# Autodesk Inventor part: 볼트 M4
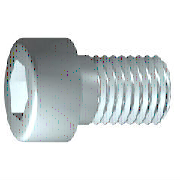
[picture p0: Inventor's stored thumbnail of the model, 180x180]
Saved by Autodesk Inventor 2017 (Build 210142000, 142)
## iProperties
IsCustomPart: 0
Created: 2012-02
Part Number: 볼트 M4
Material: 강철, 연강
Description: 6각 소켓 머리 캡 나사
Document SubType Name: Modeling
Standard: ISO 4762
Designer: mduedu
Standard Revision: Fourth edition 2004-03-01
Standards Organization: ISO
Language: ko-KR
Size Designation: M4 x 12
Categories: <MemberInstance><Categories><Category DisplayName="조임쇠" InternalName="e4da775c-781d-43d5-af7c-5136215cf5a6" Mnemonic="FSTN"><Category DisplayName="볼트" InternalN
Density: 7.75 g/cm^3
Appearance: 강철
Author: mduedu
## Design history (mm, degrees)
sketch "스케치1"
  geometry: L1 (-1, 0)-(12, 0); L2 (12, 0)-(12, 2); L3 (12, 2)-(1.75, 2); L4 (1.75, 2)-(1.32, 2); L5 (1.32, 2)-(0, 2); L6 (0, 2)-(0, 3.5); L7 (0, 3.5)-(-4, 3.5); L8 (-4, 3.5)-(-4, 1.732); L9 (-4, 1.732)-(-2, 1.732); L10 (-2, 1.732)-(-1, 0); L11 (-7.2, 0)-(15.2, 0) reference; L12 (0, -0.7)-(0, 4.2) reference; L13 (1.75, 2)-(0, 2)
  constraints: 22 end point, 6 parallel, 2 collinear, 2 perpendicular, 1 horizontal, 1 point on line
  dimensions: "d1" = 10.25 distance from line of L3.end L2 (= GEL); "d2" = 0.42952 distance of L4.end L3.end (computed from GAL); "d3" = 4 distance between parallel lines of L8 L6 (= KOH); "d4" = 2 distance of L8.end L9.end (= INTI); "d5" = 60 deg angle of L10 L1; "d6" = 4 diameter of L3 L1 (= GD); "d7" = 4 diameter of L5 L1 (= BDM); "d8" = 3.4641 diameter of L9 L1 (= 1.1547 x SW); "d9" = 7 diameter of L7 L1 (= KOD); "d26" = 12 distance between parallel lines of L12 L2 (= NLG)
revolve "본체" sketch "스케치1" stored, may be unused: angle "d10" = 90 deg
sketch "스케치2"
  geometry: L1 (0, -4.9)-(0, 4.9) reference; L2 (-4.9, 0)-(4.9, 0) reference; L3 (1.732, 0)-(0.866, -1.5); L4 (0.866, -1.5)-(-0.866, -1.5); L5 (-0.866, -1.5)-(-1.732, 0); L6 (-1.732, 0)-(-0.866, 1.5); L7 (-0.866, 1.5)-(0.866, 1.5); L8 (0.866, 1.5)-(1.732, 0); 2 further points
  constraints: 12 end point, 1 coincident, 1 horizontal alignment, 1 point on line, 12 other
extrude "슬롯" join sketch "스케치2" stored distance "d11" = 10; taper "d12" = 0 deg
workplane "Work Plane1"
fillet "Fillet2" dims "d30" = 0.1 (= R)
body "Solid1"
fillet "모깎기1" dims "d17" = 0.4 (= RR)
feature "스레드" dims "d13" = 10.25 (= GEL), "d14" = 0
chamfer "모따기1" distance "d15" = 0.42941 (= -0.5 x SPD + 0.5 x GD); stored, may be unused: second distance "d16" = 0.42941 (= GUL), angle "d27" = 45 deg
other parameters: "GD" = 4 [user parameter; used in 2 equation terms], "NLG" = 12 [user parameter; used in 1 equation term], "GEL" = 10.25 [user parameter; used in 2 equation terms], "KOD" = 7 [user parameter; used in 1 equation term], "KOH" = 4 [user parameter; used in 1 equation term], "INTI" = 2 [user parameter; used in 1 equation term], "GAL" = 0.42941 (= 0.61345 x PTC) [user parameter; used in 1 equation term], "GUL" = 0.42941 (= 0.61345 x PTC) [user parameter; used in 1 equation term], "BDM" = 4 (= NND) [user parameter; used in 1 equation term], "SW" = 3 [user parameter; used in 2 equation terms], "RR" = 0.4 [user parameter; used in 1 equation term], "SPD" = 3.14117 (= NND - 1.2269 x PTC) [user parameter; used in 1 equation term], "d19" = 0, "d28" = 0, "d29" = 0, "R" = 0.1 [user parameter; used in 1 equation term], "TOA" = 30 deg [user parameter], "GD1" = 3.14117 (= THREADDIA - 1.2269 x PTC) [user parameter], "THREADDIA" = 4 [user parameter; used in 1 equation term], "FAWI" = 45 deg [user parameter], "TPU" = 14.28571 (computed from PTC) [user parameter], "PTC" = 0.7 [user parameter; used in 5 equation terms], "NND" = 4 [user parameter; used in 2 equation terms], "E0" = 3.465 (= 1.155 x SW) [user parameter]
